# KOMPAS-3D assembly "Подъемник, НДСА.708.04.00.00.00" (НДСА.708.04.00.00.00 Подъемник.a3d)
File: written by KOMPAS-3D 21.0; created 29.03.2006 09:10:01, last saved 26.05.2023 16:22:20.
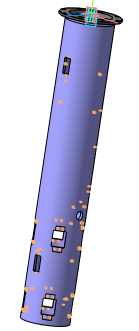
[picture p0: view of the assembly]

Document properties: Полное имя файла: C:\Users\s.pischagina\Desktop\PLM\НДСА.708.04.00.00.00 Подъемник.a3d; Автор: Устинов А.В.; Организация: Эсто-вакуум

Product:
- Part/product: Подъемник  | designation НДСА.708.04.00.00.00
    Масса: 45.357855
    additional columns: <item xmlns="http://appius.ru/pdm" xmlns:xs="http://www.w3.org/2001/XMLSchema" x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; <item xmlns="http://appius.ru/pdm" xmlns:xs="http://www.w3.org/2001/XMLSchema" x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; <item xmlns="http://appius.ru/pdm" xmlns:xs="http://www.w3.org/2001/XMLSchema" x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; <item xmlns="http://appius.ru/pdm" xmlns:xs="http://www.w3.org/2001/XMLSchema" x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; <item xmlns="http://appius.ru/pdm" xmlns:xs="http://www.w3.org/2001/XMLSchema" x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; <item xmlns="http://appius.ru/pdm" xmlns:xs="http://www.w3.org/2001/XMLSchema" x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
  - Component [detail]: Труба  | designation НДСА.708.04.00.00.01  | pos. 2  | Материал: Труба$d180х10 ГОСТ 8732-78;20 ГОСТ 8731-74$ (density 7859 kg/m3); Масса: 43.448229; additional columns: <item xmlns="http://appius.ru/pdm" xmlns:xs="http://www.w3.org/2001/XMLSchema" x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; <item xmlns="http://appius.ru/pdm" xmlns:xs="http://www.w3.org/2001/XMLSchema" x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; <item xmlns="http://appius.ru/pdm" xmlns:xs="http://www.w3.org/2001/XMLSchema" x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; <item xmlns="http://appius.ru/pdm" xmlns:xs="http://www.w3.org/2001/XMLSchema" x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; <item xmlns="http://appius.ru/pdm" xmlns:xs="http://www.w3.org/2001/XMLSchema" x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; <item xmlns="http://appius.ru/pdm" xmlns:xs="http://www.w3.org/2001/XMLSchema" x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; source file: НДСА.708.04.00.00.01 Труба.CDW, НДСА.708.04.00.00.01 Труба.m3d
  - Component [detail]: Фланец  | designation НДСА.014.01.08.05.01  | pos. 1  | Материал: Сталь 20 ГОСТ 1050-88 (density 7859 kg/m3); Масса: 1.909626; Форматы листов документа: A4; additional columns: <item xmlns="http://appius.ru/pdm" xmlns:xs="http://www.w3.org/2001/XMLSchema" x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; <item xmlns="http://appius.ru/pdm" xmlns:xs="http://www.w3.org/2001/XMLSchema" x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; <item xmlns="http://appius.ru/pdm" xmlns:xs="http://www.w3.org/2001/XMLSchema" x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; <item xmlns="http://appius.ru/pdm" xmlns:xs="http://www.w3.org/2001/XMLSchema" x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; <item xmlns="http://appius.ru/pdm" xmlns:xs="http://www.w3.org/2001/XMLSchema" x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; <item xmlns="http://appius.ru/pdm" xmlns:xs="http://www.w3.org/2001/XMLSchema" x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; source file: НДСА.014.01.08.05.01 Фланец.CDW, НДСА.014.01.08.05.01 Фланец.m3d

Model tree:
1. Плоскость XY
2. Плоскость ZX
3. Плоскость ZY
4. Начало координат
5. Плоскость под углом:1
     Угол = 45
6. Смещенная плоскость:1
     Расстояние = 90
7. Эскиз:1
8. Элемент выдавливания:1
     Расстояние 2 = 1.5
9. Эскиз:2
10. Элемент выдавливания:2
     Расстояние 1 = 164.835
11. Условное изображение резьбы:1  (with: Элемент выдавливания:2)  (labels: 8x1,25)
     Длина резьбы = 9.73453; Шаг резьбы = 1.25; Номинальный диаметр резьбы = 8
12. Подгонка:1  (with: Элемент выдавливания:2)
13. Условное изображение резьбы:2  (with: Элемент выдавливания:2)  (labels: 8x1,25)
     Длина резьбы = 9.73453; Шаг резьбы = 1.25; Номинальный диаметр резьбы = 8
14. Подгонка:2  (with: Элемент выдавливания:2)
15. Условное изображение резьбы:3  (with: Элемент выдавливания:2)  (labels: 8x1,25)
     Длина резьбы = 9.73453; Шаг резьбы = 1.25; Номинальный диаметр резьбы = 8
16. Подгонка:3  (with: Элемент выдавливания:2)
17. Условное изображение резьбы:4  (with: Элемент выдавливания:2)  (labels: 8x1,25)
     Длина резьбы = 9.73453; Шаг резьбы = 1.25; Номинальный диаметр резьбы = 8
18. Подгонка:4  (with: Элемент выдавливания:2)
19. Условное изображение резьбы:5  (with: Элемент выдавливания:2)  (labels: 8x1,25)
     Длина резьбы = 9.73453; Шаг резьбы = 1.25; Номинальный диаметр резьбы = 8
20. Подгонка:5  (with: Элемент выдавливания:2)
21. Условное изображение резьбы:6  (with: Элемент выдавливания:2)  (labels: 8x1,25)
     Длина резьбы = 9.73453; Шаг резьбы = 1.25; Номинальный диаметр резьбы = 8
22. Подгонка:6  (with: Элемент выдавливания:2)
23. Условное изображение резьбы:7  (with: Элемент выдавливания:2)  (labels: 8x1,25)
     Длина резьбы = 9.12746; Шаг резьбы = 1.25; Номинальный диаметр резьбы = 8
24. Подгонка:7  (with: Элемент выдавливания:2)
25. Условное изображение резьбы:8  (with: Элемент выдавливания:2)  (labels: 8x1,25)
     Длина резьбы = 9.12746; Шаг резьбы = 1.25; Номинальный диаметр резьбы = 8
26. Подгонка:8  (with: Элемент выдавливания:2)
27. Массив по концентрической сетке:1  (with: Элемент выдавливания:1, Элемент выдавливания:2)  (labels: Плоскость под углом:1; Смещенная плоскость:1; Плоскость под углом:1)  (2 pattern instances)
28. Элемент выдавливания:1  (with: Элемент выдавливания:2)  (labels: Плоскость под углом:1; Смещенная плоскость:1; Плоскость под углом:1)
29. Элемент выдавливания:1  (with: Элемент выдавливания:2)  (labels: Плоскость под углом:1; Смещенная плоскость:1; Плоскость под углом:1)
30. Эскиз:3
31. Элемент выдавливания:3
32. Условное изображение резьбы:9  (with: Элемент выдавливания:3)  (labels: 4,057772x0,7)
     Длина резьбы = 10; Шаг резьбы = 0.7; Номинальный диаметр резьбы = 4.05777
33. Подгонка:9  (with: Элемент выдавливания:3)
34. Плоскость под углом:2
     Угол = 20
35. Эскиз:4
36. Элемент выдавливания:4
     Расстояние 1 = 125.664
37. Массив по концентрической сетке:2  (with: Элемент выдавливания:4)  (labels: Плоскость под углом:2)  (2 pattern instances)
     Шаг 2 = 40
38. Условное изображение резьбы:12  (with: Элемент выдавливания:4)  (labels: 8x1,25)
     Длина резьбы = 10; Шаг резьбы = 1.25; Номинальный диаметр резьбы = 8
39. Подгонка:12  (with: Элемент выдавливания:4)
40. Условное изображение резьбы:13  (with: Элемент выдавливания:4)  (labels: 8x1,25)
     Длина резьбы = 10.1001; Шаг резьбы = 1.25; Номинальный диаметр резьбы = 8
41. Подгонка:13  (with: Элемент выдавливания:4)
42. Условное изображение резьбы:14  (with: Элемент выдавливания:4)  (labels: 8x1,25)
     Длина резьбы = 10.1001; Шаг резьбы = 1.25; Номинальный диаметр резьбы = 8
43. Подгонка:14  (with: Элемент выдавливания:4)
44. Условное изображение резьбы:15  (with: Элемент выдавливания:4)  (labels: 8x1,25)
     Длина резьбы = 10.1001; Шаг резьбы = 1.25; Номинальный диаметр резьбы = 8
45. Подгонка:15  (with: Элемент выдавливания:4)
46. Плоскость под углом:3
     Угол = 10
47. Эскиз:5
48. Элемент выдавливания:5
     Расстояние 2 = 119.223
49. Условное изображение резьбы:16  (with: Элемент выдавливания:5)  (labels: 6x1)
     Длина резьбы = 10.0563; Шаг резьбы = 1; Номинальный диаметр резьбы = 6
50. Подгонка:16  (with: Элемент выдавливания:5)
51. Условное изображение резьбы:17  (with: Элемент выдавливания:5)  (labels: 6x1)
     Длина резьбы = 10.0563; Шаг резьбы = 1; Номинальный диаметр резьбы = 6
52. Подгонка:17  (with: Элемент выдавливания:5)
53. Эскиз:6
54. Элемент выдавливания:6
     Расстояние 1 = 116
55. Условное изображение резьбы:18  (with: Элемент выдавливания:6)  (labels: 8x1,25)
     Длина резьбы = 10.1001; Шаг резьбы = 1.25; Номинальный диаметр резьбы = 8
56. Подгонка:18  (with: Элемент выдавливания:6)
57. Условное изображение резьбы:19  (with: Элемент выдавливания:6)  (labels: 8x1,25)
     Длина резьбы = 10.1001; Шаг резьбы = 1.25; Номинальный диаметр резьбы = 8
58. Подгонка:19  (with: Элемент выдавливания:6)
59. Условное изображение резьбы:20  (with: Элемент выдавливания:6)  (labels: 8x1,25)
     Длина резьбы = 10.1001; Шаг резьбы = 1.25; Номинальный диаметр резьбы = 8
60. Подгонка:20  (with: Элемент выдавливания:6)
61. Условное изображение резьбы:21  (with: Элемент выдавливания:6)  (labels: 8x1,25)
     Длина резьбы = 10.1001; Шаг резьбы = 1.25; Номинальный диаметр резьбы = 8
62. Подгонка:21  (with: Элемент выдавливания:6)
63. Условное изображение резьбы:22  (with: Элемент выдавливания:6)  (labels: 8x1,25)
     Длина резьбы = 10; Шаг резьбы = 1.25; Номинальный диаметр резьбы = 8
64. Подгонка:22  (with: Элемент выдавливания:6)
65. Условное изображение резьбы:23  (with: Элемент выдавливания:6)  (labels: 8x1,25)
     Длина резьбы = 10; Шаг резьбы = 1.25; Номинальный диаметр резьбы = 8
66. Подгонка:23  (with: Элемент выдавливания:6)
67. Условное изображение резьбы:24  (with: Элемент выдавливания:6)  (labels: 8x1,25)
     Длина резьбы = 10; Шаг резьбы = 1.25; Номинальный диаметр резьбы = 8
68. Подгонка:24  (with: Элемент выдавливания:6)
69. Условное изображение резьбы:25  (with: Элемент выдавливания:6)  (labels: 8x1,25)
     Длина резьбы = 10; Шаг резьбы = 1.25; Номинальный диаметр резьбы = 8
70. Подгонка:25  (with: Элемент выдавливания:6)
71. Эскиз:7
72. Элемент выдавливания:7
     Расстояние 1 = 116
73. Эскиз:8
74. Элемент выдавливания:8
     Расстояние 2 = 116
75. Условное изображение резьбы:26  (with: Элемент выдавливания:8)  (labels: 4x0,7)
     Длина резьбы = 10; Шаг резьбы = 0.7; Номинальный диаметр резьбы = 4
76. Подгонка:26  (with: Элемент выдавливания:8)
77. Условное изображение резьбы:27  (with: Элемент выдавливания:8)  (labels: 4x0,7)
     Длина резьбы = 10.025; Шаг резьбы = 0.7; Номинальный диаметр резьбы = 4
78. Подгонка:27  (with: Элемент выдавливания:8)
79. Условное изображение резьбы:28  (with: Элемент выдавливания:8)  (labels: 4x0,7)
     Длина резьбы = 10; Шаг резьбы = 0.7; Номинальный диаметр резьбы = 4
80. Подгонка:28  (with: Элемент выдавливания:8)
81. Условное изображение резьбы:29  (with: Элемент выдавливания:8)  (labels: 4x0,7)
     Длина резьбы = 10; Шаг резьбы = 0.7; Номинальный диаметр резьбы = 4
82. Подгонка:29  (with: Элемент выдавливания:8)
83. Условное изображение резьбы:30  (with: Элемент выдавливания:8)  (labels: 4x0,7)
     Длина резьбы = 10; Шаг резьбы = 0.7; Номинальный диаметр резьбы = 4
84. Подгонка:30  (with: Элемент выдавливания:8)
85. Условное изображение резьбы:31  (with: Элемент выдавливания:8)  (labels: 4x0,7)
     Длина резьбы = 10; Шаг резьбы = 0.7; Номинальный диаметр резьбы = 4
86. Подгонка:31  (with: Элемент выдавливания:8)
87. Плоскость под углом:4
     Угол = -45
88. Эскиз:9
89. Элемент выдавливания:9
     Расстояние 2 = 165.049
90. Условное изображение резьбы:32  (with: Элемент выдавливания:9)  (labels: 4x0,7)
     Длина резьбы = 10.025; Шаг резьбы = 0.7; Номинальный диаметр резьбы = 4
91. Подгонка:32  (with: Элемент выдавливания:9)
92. Условное изображение резьбы:33  (with: Элемент выдавливания:9)  (labels: 4x0,7)
     Длина резьбы = 10; Шаг резьбы = 0.7; Номинальный диаметр резьбы = 4
93. Подгонка:33  (with: Элемент выдавливания:9)
94. Условное изображение резьбы:34  (with: Элемент выдавливания:9)  (labels: 4x0,7)
     Длина резьбы = 10; Шаг резьбы = 0.7; Номинальный диаметр резьбы = 4
95. Подгонка:34  (with: Элемент выдавливания:9)
96. Условное изображение резьбы:35  (with: Элемент выдавливания:9)  (labels: 4x0,7)
     Длина резьбы = 10.025; Шаг резьбы = 0.7; Номинальный диаметр резьбы = 4
97. Подгонка:35  (with: Элемент выдавливания:9)
98. Эскиз:10
99. Элемент выдавливания:10
     Расстояние 1 = 116
100. Условное изображение резьбы:37  (with: Элемент выдавливания:10)  (labels: 4x0,7)
     Длина резьбы = 10; Шаг резьбы = 0.7; Номинальный диаметр резьбы = 4
101. Подгонка:37  (with: Элемент выдавливания:10)
102. Условное изображение резьбы:38  (with: Элемент выдавливания:10)  (labels: 4x0,7)
     Длина резьбы = 10; Шаг резьбы = 0.7; Номинальный диаметр резьбы = 4
103. Подгонка:38  (with: Элемент выдавливания:10)
104. Скругление:1  (with: Элемент выдавливания:8)
     Радиус = 4; Полуось 2 = 1; Коэффициент = 0.5; Хорда = 1
105. Условное изображение резьбы:39  (with: Элемент выдавливания:2, Элемент выдавливания:1, Подгонка:1)  (labels: M8; cil0_24705-2004 coarse)
     Длина резьбы = 9.73453; Шаг резьбы = 1.25; Номинальный диаметр резьбы = 8
106. Условное изображение резьбы:40  (with: Элемент выдавливания:2, Элемент выдавливания:1, Подгонка:2)  (labels: M8; cil0_24705-2004 coarse)
     Длина резьбы = 9.73453; Шаг резьбы = 1.25; Номинальный диаметр резьбы = 8
107. Условное изображение резьбы:41  (with: Элемент выдавливания:2, Элемент выдавливания:1, Подгонка:3)  (labels: M8; cil0_24705-2004 coarse)
     Длина резьбы = 9.73453; Шаг резьбы = 1.25; Номинальный диаметр резьбы = 8
108. Условное изображение резьбы:42  (with: Элемент выдавливания:2, Элемент выдавливания:1, Подгонка:4)  (labels: M8; cil0_24705-2004 coarse)
     Длина резьбы = 9.73453; Шаг резьбы = 1.25; Номинальный диаметр резьбы = 8
109. Условное изображение резьбы:43  (with: Элемент выдавливания:2, Элемент выдавливания:1, Подгонка:5)  (labels: M8; cil0_24705-2004 coarse)
     Длина резьбы = 9.73453; Шаг резьбы = 1.25; Номинальный диаметр резьбы = 8
110. Условное изображение резьбы:44  (with: Элемент выдавливания:2, Элемент выдавливания:1, Подгонка:6)  (labels: M8; cil0_24705-2004 coarse)
     Длина резьбы = 9.73453; Шаг резьбы = 1.25; Номинальный диаметр резьбы = 8
111. Условное изображение резьбы:45  (with: Элемент выдавливания:2, Элемент выдавливания:1, Подгонка:7)  (labels: M8; cil0_24705-2004 coarse)
     Длина резьбы = 9.12746; Шаг резьбы = 1.25; Номинальный диаметр резьбы = 8
112. Условное изображение резьбы:46  (with: Элемент выдавливания:2, Элемент выдавливания:1, Подгонка:8)  (labels: M8; cil0_24705-2004 coarse)
     Длина резьбы = 9.12746; Шаг резьбы = 1.25; Номинальный диаметр резьбы = 8
113. Условное изображение резьбы:47  (with: Элемент выдавливания:2, Элемент выдавливания:1, Подгонка:9)  (labels: M8; cil0_24705-2004 coarse)
     Длина резьбы = 9.73453; Шаг резьбы = 1.25; Номинальный диаметр резьбы = 8
114. Условное изображение резьбы:48  (with: Элемент выдавливания:2, Элемент выдавливания:1)  (labels: M8; cil0_24705-2004 coarse)
     Длина резьбы = 9.73453; Шаг резьбы = 1.25; Номинальный диаметр резьбы = 8
115. Подгонка:10  (with: Элемент выдавливания:2)
116. Условное изображение резьбы:49  (with: Элемент выдавливания:2, Элемент выдавливания:1)  (labels: M8; cil0_24705-2004 coarse)
     Длина резьбы = 9.73453; Шаг резьбы = 1.25; Номинальный диаметр резьбы = 8
117. Подгонка:11  (with: Элемент выдавливания:2)
118. Условное изображение резьбы:50  (with: Элемент выдавливания:2, Элемент выдавливания:1, Подгонка:12)  (labels: M8; cil0_24705-2004 coarse)
     Длина резьбы = 9.73453; Шаг резьбы = 1.25; Номинальный диаметр резьбы = 8
119. Условное изображение резьбы:51  (with: Элемент выдавливания:2, Элемент выдавливания:1, Подгонка:13)  (labels: M8; cil0_24705-2004 coarse)
     Длина резьбы = 9.73453; Шаг резьбы = 1.25; Номинальный диаметр резьбы = 8
120. Условное изображение резьбы:52  (with: Элемент выдавливания:2, Элемент выдавливания:1, Подгонка:14)  (labels: M8; cil0_24705-2004 coarse)
     Длина резьбы = 9.73453; Шаг резьбы = 1.25; Номинальный диаметр резьбы = 8
121. Условное изображение резьбы:53  (with: Элемент выдавливания:2, Элемент выдавливания:1, Подгонка:15)  (labels: M8; cil0_24705-2004 coarse)
     Длина резьбы = 9.73453; Шаг резьбы = 1.25; Номинальный диаметр резьбы = 8
122. Условное изображение резьбы:54  (with: Элемент выдавливания:2, Элемент выдавливания:1, Подгонка:16)  (labels: M8; cil0_24705-2004 coarse)
     Длина резьбы = 9.73453; Шаг резьбы = 1.25; Номинальный диаметр резьбы = 8
123. Условное изображение резьбы:55  (with: Элемент выдавливания:2, Элемент выдавливания:1, Подгонка:17)  (labels: M8; cil0_24705-2004 coarse)
     Длина резьбы = 9.12746; Шаг резьбы = 1.25; Номинальный диаметр резьбы = 8
124. Условное изображение резьбы:56  (with: Элемент выдавливания:2, Элемент выдавливания:1, Подгонка:18)  (labels: M8; cil0_24705-2004 coarse)
     Длина резьбы = 9.73453; Шаг резьбы = 1.25; Номинальный диаметр резьбы = 8
125. Условное изображение резьбы:57  (with: Элемент выдавливания:2, Элемент выдавливания:1, Подгонка:19)  (labels: M8; cil0_24705-2004 coarse)
     Длина резьбы = 9.73453; Шаг резьбы = 1.25; Номинальный диаметр резьбы = 8
126. Условное изображение резьбы:58  (with: Элемент выдавливания:2, Элемент выдавливания:1, Подгонка:20)  (labels: M8; cil0_24705-2004 coarse)
     Длина резьбы = 9.73453; Шаг резьбы = 1.25; Номинальный диаметр резьбы = 8
127. Условное изображение резьбы:59  (with: Элемент выдавливания:2, Элемент выдавливания:1, Подгонка:21)  (labels: M8; cil0_24705-2004 coarse)
     Длина резьбы = 9.73453; Шаг резьбы = 1.25; Номинальный диаметр резьбы = 8
128. Условное изображение резьбы:60  (with: Элемент выдавливания:2, Элемент выдавливания:1, Подгонка:22)  (labels: M8; cil0_24705-2004 coarse)
     Длина резьбы = 9.73453; Шаг резьбы = 1.25; Номинальный диаметр резьбы = 8
129. Условное изображение резьбы:61  (with: Элемент выдавливания:2, Элемент выдавливания:1, Подгонка:23)  (labels: M8; cil0_24705-2004 coarse)
     Длина резьбы = 9.12746; Шаг резьбы = 1.25; Номинальный диаметр резьбы = 8
130. Условное изображение резьбы:62  (with: Элемент выдавливания:2, Элемент выдавливания:1, Подгонка:24)  (labels: M8; cil0_24705-2004 coarse)
     Длина резьбы = 9.12746; Шаг резьбы = 1.25; Номинальный диаметр резьбы = 8
131. Сечение поверхностью:1  (labels: Труба$d180х10 ГОСТ 8732-78;20 ГОСТ 8731-74$)

Expressions: 1051+15
Referenced files in C:\Users\s.pischagina\Desktop\PLM\: НДСА.014.01.08.05.01 Фланец.m3d, НДСА.014.01.08.05.01 Фланец.CDW, НДСА.708.04.00.00.01 Труба.m3d, НДСА.708.04.00.00.01 Труба.CDW
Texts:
  НДСА.014.01.08.05.01
  НДСА.708.04.00.00.01
  НДСА.708.04.00.00.00
  НДСА.014.01.08.05.01 Фланец
  НДСА.708.04.00.00.01 Труба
